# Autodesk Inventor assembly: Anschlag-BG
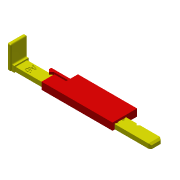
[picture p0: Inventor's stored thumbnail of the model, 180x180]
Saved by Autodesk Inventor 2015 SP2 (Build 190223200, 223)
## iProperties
Created: 2017-07
Part Number: Anschlag-BG
Document SubType Name: Assembly
Designer: UR
Author: UR
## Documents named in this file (3)
- X:\Tresor_SSD\Arbeit\Unterricht\Stoff\Inventor\Locher 05 Version 2\Anschlag-BG.iam
- X:\Tresor_SSD\Arbeit\Unterricht\Stoff\Inventor\Locher 05 Version 2\Anschlagschieber.ipt
- X:\Tresor_SSD\Arbeit\Unterricht\Stoff\Inventor\Locher 05 Version 2\Anschlagfuehrung.ipt
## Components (2 placed, 2 different names)
1. Anschlagschieber:1 — Passend:10, Fluchtend:1, Passend:11
2. Anschlagfuehrung:1 — Passend:10, Fluchtend:1, Passend:11
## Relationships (3: Mate 2, Flush 1)
- Passend:10 [Mate]: Anschlagschieber:1 ↔ Anschlagfuehrung:1
- Fluchtend:1 [Flush]: Anschlagschieber:1 ↔ Anschlagfuehrung:1
- Passend:11 [Mate]: Anschlagschieber:1 ↔ Anschlagfuehrung:1
